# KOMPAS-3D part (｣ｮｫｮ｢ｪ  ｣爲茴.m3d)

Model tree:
1. Эскиз:1
2. Операция выдавливания:1
     Расстояние 1 = 16
3. Эскиз:2
4. Вырезать элемент выдавливания:1
     Расстояние 1 = 14.4
5. Эскиз:3
6. Операция выдавливания:2
     Расстояние 1 = 2; Расстояние 2 = 124
7. Скругление:1
     Радиус = 5
8. Скругление:2
     Радиус = 5
9. Скругление:3
     Радиус = 5
10. Эскиз:4
11. Операция выдавливания:3
     Расстояние 1 = 5; Расстояние 2 = 115
12. Эскиз:5
13. Эскиз:6
14. Операция выдавливания:4
     Расстояние 1 = 2
15. Скругление:4
     Радиус = 3
16. Эскиз:7
17. Операция выдавливания:5
     Расстояние 1 = 0.5
